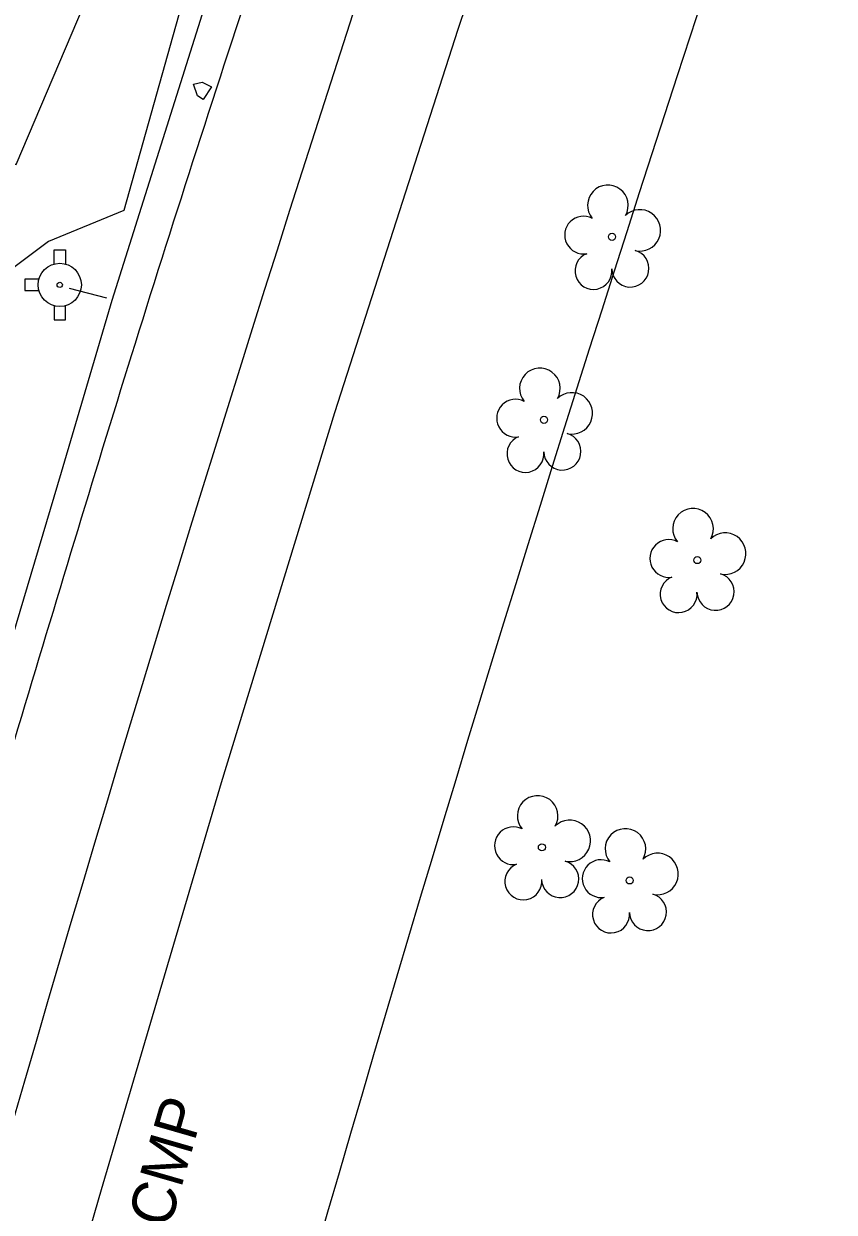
# Model space of a CAD drawing. Extents: x 553786 to 558838, y 502329 to 507342.
# Drawn here: x 557282.1 to 557356.3, y 506039.9 to 506148.7 of the extents above; entities that cross this region are included whole.
import ezdxf

# ---------------------------------------------------------------- set-up
doc = ezdxf.new("R2010")
doc.units = 0
for name, color, linetype in [('Exist Hydro Jurisdictional Stream or Body of Water', 7, 'Continuous'), ('Exist Structure Minor Pipes CMP 15 Inch Text', 7, 'Continuous'), ('Exist Vegetation Hedge Row', 7, 'Continuous'), ('Exist Vegetation Tree CELL', 7, 'Continuous'), ('Prop Drainage Structure Junction Box with Manhole Label', 7, 'Continuous'), ('Prop Drainage Structure Pipe Alternate 24in', 7, 'Continuous'), ('Prop Drainage Structure Pipe Alternate 36in', 7, 'Continuous'), ('Prop Drainage Structure Pipe RCP 15in Class III Label', 7, 'Continuous'), ('Sheet Layout Plan Border', 7, 'Continuous')]:
    doc.layers.add(name, color=color, linetype=linetype)

# ---------------------------------------------------------------- blocks, each defined once
blk = doc.blocks.new('EXIST UTILITIES WATER FIRE HYDRANT')
at = {"layer": 'Prop Drainage Structure Junction Box with Manhole Label'}
blk.add_line((0, 0), (0, 0), dxfattribs=at)
for points in [[(-0.01025, 0.03825), (-0.01025, 0.064), (0.01025, 0.064), (0.01025, 0.03775)], [(-0.03825, 0.01025), (-0.064, 0.01025), (-0.064, -0.01025), (-0.03825, -0.01025)], [(-0.01025, -0.03825), (-0.01025, -0.064), (0.01025, -0.064), (0.01025, -0.03775)]]:
    blk.add_lwpolyline(points, dxfattribs=at)
for radius in [0.03954, 0.00485]:
    blk.add_circle((0, 0), radius, dxfattribs=at)

msp = doc.modelspace()

# ---------------------------------------------------------------- linework, layer by layer
at = {"layer": 'Exist Hydro Jurisdictional Stream or Body of Water'}
msp.add_lwpolyline([(557298.55, 506141.73), (557298.02, 506142.06), (557297.67, 506143.15), (557298.46, 506143.33), (557299.32, 506142.89), (557298.55, 506141.73)], dxfattribs=at)
at = {"layer": 'Exist Vegetation Hedge Row'}
msp.add_lwpolyline([(557257.52, 506143.05), (557281.42, 506135.8), (557295.59, 506169.11), (557307.61, 506205.03), (557318.09, 506230.65), (557323.08, 506231.55), (557314.31, 506213.54), (557291.28, 506131.57), (557284.4, 506128.73), (557274.92, 506121.65), (557268.3, 506125.83)], dxfattribs=at)
at = {"layer": 'Exist Vegetation Tree CELL'}
for p, q in [((557335.99, 506129.17), (557335.99, 506129.17)), ((557329.76, 506112.42), (557329.76, 506112.42)), ((557343.8, 506099.58), (557343.8, 506099.58)), ((557329.57, 506073.29), (557329.57, 506073.29)), ((557337.61, 506070.26), (557337.61, 506070.26))]:
    msp.add_line(p, q, dxfattribs=at)
for centre in [(557335.99, 506129.17), (557329.76, 506112.42), (557343.8, 506099.58), (557329.57, 506073.29), (557337.61, 506070.26)]:
    msp.add_circle(centre, 0.326, dxfattribs=at)
for centre, radius, start, end in [((557335.61, 506132.05), 1.86, 330.1651, 219.7134), ((557333.39, 506129.33), 1.73, 62.6636, 279.3457), ((557338.54, 506129.76), 1.9, 257.1011, 134.1999), ((557334.29, 506126.05), 1.69, 111.5671, 6.231), ((557337.67, 506126.27), 1.7, 181.2822, 74.56), ((557329.38, 506115.29), 1.86, 330.1651, 219.7134), ((557332.31, 506113.01), 1.9, 257.1011, 134.1999), ((557327.16, 506112.57), 1.73, 62.6636, 279.3457), ((557331.44, 506109.52), 1.7, 181.2822, 74.56), ((557328.06, 506109.3), 1.69, 111.5671, 6.231), ((557343.41, 506102.45), 1.86, 330.1651, 219.7134), ((557341.19, 506099.73), 1.73, 62.6636, 279.3457), ((557346.35, 506100.17), 1.9, 257.1011, 134.1999), ((557345.47, 506096.68), 1.7, 181.2822, 74.56), ((557342.09, 506096.46), 1.69, 111.5671, 6.231), ((557329.18, 506076.16), 1.86, 330.1651, 219.7134), ((557332.12, 506073.88), 1.9, 257.1011, 134.1999), ((557326.96, 506073.44), 1.73, 62.6636, 279.3457), ((557337.22, 506073.14), 1.86, 330.1651, 219.7134), ((557331.24, 506070.39), 1.7, 181.2822, 74.56), ((557335, 506070.42), 1.73, 62.6636, 279.3457), ((557340.16, 506070.85), 1.9, 257.1011, 134.1999), ((557327.87, 506070.17), 1.69, 111.5671, 6.231), ((557335.9, 506067.14), 1.69, 111.5671, 6.231), ((557339.28, 506067.37), 1.7, 181.2822, 74.56)]:
    msp.add_arc(centre, radius, start, end, dxfattribs=at)
at = {"layer": 'Prop Drainage Structure Pipe Alternate 24in'}
msp.add_line((557289.73, 506123.55), (557286.3, 506124.43), dxfattribs=at)
msp.add_lwpolyline([(557243.68, 505962.79), (557252.06, 505988.15), (557258.47, 506016.07), (557267.52, 506046.71), (557278.33, 506083.32), (557285.57, 506107.63), (557290.22, 506123.38), (557303.51, 506165.49), (557316.86, 506202.67), (557333.92, 506253.08)], dxfattribs=at)
at = {"layer": 'Prop Drainage Structure Pipe Alternate 36in'}
msp.add_lwpolyline([(557212.46, 505720.35), (557215.05, 505733.68), (557221.79, 505766.55), (557228.98, 505801.8), (557236.69, 505837.01), (557244.16, 505869.62), (557253.02, 505906.71), (557261.61, 505941.19), (557270.21, 505974.95), (557279.45, 506008.27), (557289.23, 506041.96), (557300.22, 506079.21), (557310.6, 506113.1), (557321.89, 506148.18), (557334.22, 506184.7)], dxfattribs=at)
msp.add_spline([(557270.81, 506048.05), (557281.94, 506085.29), (557292.35, 506119.45), (557303.76, 506154.85), (557316.1, 506191.39)], degree=3, dxfattribs=at)
at = {"layer": 'Prop Drainage Structure Pipe RCP 15in Class III Label'}
for radius in [3304.04, 3244.04]:
    msp.add_arc((560426.05, 505137.84), radius, 158.42006, 166.90458, dxfattribs=at)
at = {"layer": 'Sheet Layout Plan Border'}
msp.add_arc((560426.05, 505137.84), 3274.04, 158.42006, 166.90458, dxfattribs=at)

# ---------------------------------------------------------------- block references
at = {"layer": 'Prop Drainage Structure Junction Box with Manhole Label', "xscale": 50, "yscale": 50}
msp.add_blockref('EXIST UTILITIES WATER FIRE HYDRANT', (557285.42, 506124.77), dxfattribs=at)

# ---------------------------------------------------------------- texts
at = {"layer": 'Exist Structure Minor Pipes CMP 15 Inch Text'}
msp.add_text('15" CMP', height=4, rotation=73.9033, dxfattribs=at).set_placement((557292.86, 506029.32))

doc.saveas('drawing.dxf')
